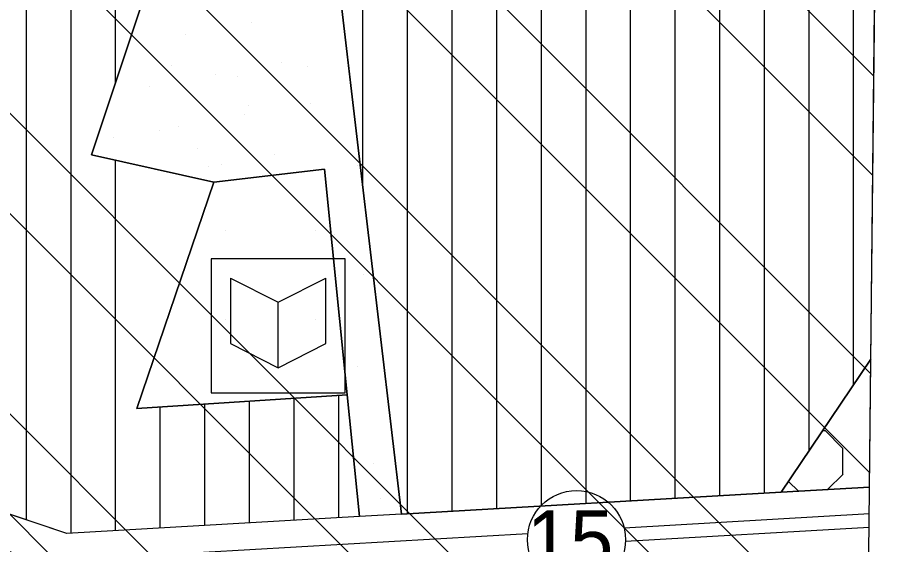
# Model space of a CAD drawing. Extents: x 419109 to 421295, y 4452223 to 4457798.
# Drawn here: x 421068.1 to 421266.4, y 4454284 to 4454402 of the extents above; entities that cross this region are included whole.
import ezdxf

# ---------------------------------------------------------------- set-up
doc = ezdxf.new("R2010")
doc.units = 0
for name, color, linetype in [('ADA', 7, 'Continuous'), ('ADAKENARI', 7, 'Continuous'), ('Default', 7, 'Continuous'), ('KALDIRIM', 7, 'Continuous'), ('KD_DAIRE', 7, 'Continuous'), ('KD_YGEN', 7, 'Continuous'), ('LJ_SEMBOL', 7, 'Continuous'), ('PAFTALAMA', 7, 'Continuous'), ('PL_AYA_AGACLANDIRIL', 7, 'Continuous'), ('PL_AYA_PARK_DINLENME', 7, 'Continuous'), ('PL_KON_MEV_350', 7, 'Continuous'), ('PL_SAY_KULTUR_TESIS', 7, 'Continuous'), ('SN_TR_SIVILASMA', 7, 'Continuous'), ('TR_AGACALANI', 7, 'Continuous'), ('TR_KULTURELTESIS', 7, 'Continuous'), ('TR_ORTAYOGUNKONUT', 7, 'Continuous'), ('TR_PARKALANI', 7, 'Continuous')]:
    doc.layers.add(name, color=color, linetype=linetype)

# ---------------------------------------------------------------- blocks, each defined once
blk = doc.blocks.new('POINT_DISPLAY')
at = {"layer": 'Default'}
blk.add_line((0, 0), (0, 0), dxfattribs=at)

msp = doc.modelspace()

# ---------------------------------------------------------------- linework, layer by layer
at = {"layer": 'ADA'}
for p, q in [((421144.89, 4454369.02), (421115.5, 4454618.79)), ((421098.33, 4454412.34), (421084.63, 4454371.25)), ((421084.63, 4454371.25), (421112.03, 4454365.16)), ((421112.03, 4454365.16), (421136.91, 4454368.08)), ((421136.91, 4454368.08), (421141.97, 4454317.46)), ((421154.1, 4454290.74), (421144.89, 4454369.02)), ((421112.03, 4454365.16), (421094.78, 4454314.42)), ((421259.38, 4454325.45), (421239.25, 4454295.67)), ((421094.78, 4454314.42), (421141.97, 4454317.46)), ((421141.97, 4454317.46), (421144.69, 4454290.2))]:
    msp.add_line(p, q, dxfattribs=at)
at = {"layer": 'ADAKENARI'}
for p, q in [((421259.08, 4454296.82), (421239.25, 4454295.67)), ((421239.25, 4454295.67), (421154.1, 4454290.74)), ((421079.09, 4454286.4), (421061.53, 4454292.35)), ((421144.69, 4454290.2), (421079.09, 4454286.4)), ((421154.1, 4454290.74), (421144.69, 4454290.2))]:
    msp.add_line(p, q, dxfattribs=at)
at = {"layer": 'KALDIRIM'}
for p, q in [((421259.02, 4454290.81), (421204.06, 4454287.63)), ((421182.45, 4454286.37), (421078.62, 4454280.36)), ((421258.99, 4454287.8), (421204.36, 4454284.64))]:
    msp.add_line(p, q, dxfattribs=at)
msp.add_arc((421076.96, 4454309.02), 28.7, 229.2729, 273.3141, dxfattribs=at)
at = {"layer": 'KD_DAIRE'}
msp.add_circle((421193.37, 4454285.04), 11, dxfattribs=at)
at = {"layer": 'LJ_SEMBOL'}
for p, q in [((421111.49, 4454347.96), (421111.49, 4454317.96)), ((421141.49, 4454347.96), (421111.49, 4454347.96)), ((421141.49, 4454317.96), (421141.49, 4454347.96)), ((421115.8, 4454343.67), (421115.8, 4454329)), ((421115.8, 4454343.67), (421126.49, 4454338.22)), ((421126.49, 4454338.22), (421137.18, 4454343.67)), ((421137.18, 4454329), (421137.18, 4454343.67)), ((421126.49, 4454323.56), (421126.49, 4454338.22)), ((421115.8, 4454329), (421126.49, 4454323.56)), ((421126.49, 4454323.56), (421137.18, 4454329)), ((421111.49, 4454317.96), (421141.49, 4454317.96))]:
    msp.add_line(p, q, dxfattribs=at)
msp.add_lwpolyline([(421111.49, 4454317.96), (421141.49, 4454317.96), (421141.49, 4454347.96), (421111.49, 4454347.96)], close=True, dxfattribs=at)
at = {"layer": 'PAFTALAMA'}
msp.add_lwpolyline([(419138.44, 4455021.89), (419108.72, 4452245.78), (421237.47, 4452223.29), (421266.41, 4454999.4)], dxfattribs=at)
at = {"layer": 'PL_AYA_AGACLANDIRIL'}
msp.add_line((421259.08, 4454296.82), (421259.38, 4454325.45), dxfattribs=at)
msp.add_lwpolyline([(421259.38, 4454325.45), (421239.25, 4454295.67), (421259.08, 4454296.82)], dxfattribs=at)
at = {"layer": 'PL_AYA_PARK_DINLENME'}
msp.add_lwpolyline([(421098.33, 4454412.34), (421112.39, 4454474.83), (421121.16, 4454513.82), (421068.9, 4454528.03), (421084.13, 4454581.81), (421084.97, 4454620.78), (421115.5, 4454618.79), (421144.89, 4454369.02), (421154.1, 4454290.74), (421144.69, 4454290.2), (421141.97, 4454317.46), (421136.91, 4454368.08), (421112.03, 4454365.16), (421084.63, 4454371.25)], close=True, dxfattribs=at)
at = {"layer": 'PL_KON_MEV_350'}
msp.add_line((421259.38, 4454325.45), (421261.92, 4454568.53), dxfattribs=at)
msp.add_lwpolyline([(421016.17, 4454625.26), (421084.97, 4454620.78), (421084.13, 4454581.81), (421068.9, 4454528.03), (421057.44, 4454490.64), (421112.39, 4454474.83), (421098.33, 4454412.34), (421084.63, 4454371.25), (421112.03, 4454365.16), (421094.78, 4454314.42), (421141.97, 4454317.46), (421144.69, 4454290.2), (421079.09, 4454286.4), (421061.53, 4454292.35), (420940.66, 4454396.41), (420954.23, 4454423), (420920.05, 4454437.89), (421002.02, 4454616.82)], close=True, dxfattribs=at)
msp.add_lwpolyline([(421262.34, 4454609.22), (421115.5, 4454618.79), (421144.89, 4454369.02), (421154.1, 4454290.74), (421239.25, 4454295.67), (421259.38, 4454325.45)], dxfattribs=at)
at = {"layer": 'PL_SAY_KULTUR_TESIS'}
msp.add_lwpolyline([(421141.97, 4454317.46), (421094.78, 4454314.42), (421112.03, 4454365.16), (421136.91, 4454368.08)], close=True, dxfattribs=at)
at = {"layer": 'SN_TR_SIVILASMA'}
for p, q in [((421259.81, 4454366.67), (420620.25, 4455006.23)), ((421260.04, 4454388.89), (420642.94, 4455005.99)), ((421259.35, 4454322.23), (420650.2, 4454931.39)), ((421259.12, 4454300.01), (420676.73, 4454882.4)), ((421258.65, 4454255.58), (420729.79, 4454784.44)), ((421258.42, 4454233.36), (420751.04, 4454740.73)), ((421257.96, 4454188.92), (420757.65, 4454689.23)), ((421257.73, 4454166.7), (420770.48, 4454653.95)), ((421257.26, 4454122.26), (420793.95, 4454585.57)), ((421257.03, 4454100.04), (420802.93, 4454554.14))]:
    msp.add_line(p, q, dxfattribs=at)
at = {"layer": 'TR_AGACALANI'}
for p, q in [((421248.62, 4454309.53), (421249.07, 4454309.53)), ((421253.11, 4454305.49), (421249.05, 4454309.55)), ((421253.11, 4454299.75), (421253.11, 4454305.49)), ((421243.1, 4454295.9), (421240.89, 4454298.11)), ((421249.67, 4454296.28), (421253.13, 4454299.73))]:
    msp.add_line(p, q, dxfattribs=at)
at = {"layer": 'TR_ORTAYOGUNKONUT'}
for p, q in [((421145.5, 4454363.79), (421145.5, 4454616.83)), ((421155.5, 4454290.82), (421155.5, 4454616.18)), ((421165.5, 4454291.4), (421165.5, 4454615.53)), ((421175.5, 4454291.98), (421175.5, 4454614.88)), ((421185.5, 4454292.56), (421185.5, 4454614.23)), ((421255.5, 4454319.71), (421255.5, 4454543.83)), ((421245.5, 4454304.92), (421245.5, 4454518.26)), ((421070.05, 4454289.46), (421070.05, 4454487.01)), ((421080.05, 4454286.45), (421080.05, 4454484.14)), ((421090.05, 4454387.5), (421090.05, 4454481.26)), ((421235.5, 4454295.46), (421235.5, 4454422.84)), ((421195.5, 4454293.14), (421195.5, 4454420.42)), ((421205.5, 4454293.72), (421205.5, 4454413.27)), ((421225.5, 4454294.88), (421225.5, 4454414.06)), ((421215.5, 4454294.3), (421215.5, 4454411.57)), ((421090.05, 4454287.03), (421090.05, 4454370.04)), ((421120.05, 4454288.77), (421120.05, 4454316.05)), ((421130.05, 4454289.35), (421130.05, 4454316.69)), ((421140.05, 4454289.93), (421140.05, 4454317.34)), ((421100.05, 4454287.61), (421100.05, 4454314.76)), ((421110.05, 4454288.19), (421110.05, 4454315.4))]:
    msp.add_line(p, q, dxfattribs=at)

# ---------------------------------------------------------------- block references
at = {"layer": 'TR_KULTURELTESIS', "xscale": 0.1, "yscale": 0.10000000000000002}
for p in [(421114.78, 4454354.42), (421134.78, 4454354.42), (421114.78, 4454334.42), (421134.78, 4454334.42)]:
    msp.add_blockref('POINT_DISPLAY', p, dxfattribs=at)
at = {"layer": 'TR_PARKALANI', "xscale": 0.1, "yscale": 0.10000000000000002}
for p in [(421120.48, 4454400.83), (421105.7, 4454398.23), (421102.57, 4454391.38), (421127.14, 4454391.85), (421112.36, 4454389.25), (421132.98, 4454391.09), (421117.34, 4454388.77), (421097.59, 4454386.64), (421119.87, 4454382.39), (421133.8, 4454382.87), (421119.02, 4454380.27), (421104.25, 4454377.67), (421099.96, 4454376.61), (421089.48, 4454375.06), (421140.46, 4454373.89), (421108.38, 4454372.75), (421125.68, 4454371.29), (421110.91, 4454368.69), (421113.87, 4454369.08), (421144.28, 4454368.79), (421139.01, 4454353.33), (421139.94, 4454344.17), (421145.67, 4454344.35), (421144.22, 4454323.79), (421150.88, 4454314.81), (421147.76, 4454302.17), (421149.42, 4454294.24)]:
    msp.add_blockref('POINT_DISPLAY', p, dxfattribs=at)

# ---------------------------------------------------------------- texts
at = {"layer": 'KD_YGEN'}
msp.add_text('15', height=13, dxfattribs=at).set_placement((421182.27, 4454278.64))

doc.saveas('drawing.dxf')
